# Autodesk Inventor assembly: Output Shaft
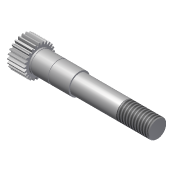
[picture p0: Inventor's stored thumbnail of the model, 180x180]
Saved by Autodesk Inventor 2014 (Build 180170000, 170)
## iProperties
Created: 2011-01
Part Number: Output Shaft
Document SubType Name: Assembly
Designer: Beta-8540w
ClientObjectVersion: 1
Author: Beta-8540w
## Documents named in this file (2)
- C:\Inventor 2014 Essentials\Assemblies\Chapter 09\Design Accelerators\Shaft c09-02.iam
- C:\Inventor 2014 Essentials\Assemblies\Chapter 09\Design Accelerators\Shaft c09-02.ipt
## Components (1 placed, 1 different names)
1. Output Shaft:1
